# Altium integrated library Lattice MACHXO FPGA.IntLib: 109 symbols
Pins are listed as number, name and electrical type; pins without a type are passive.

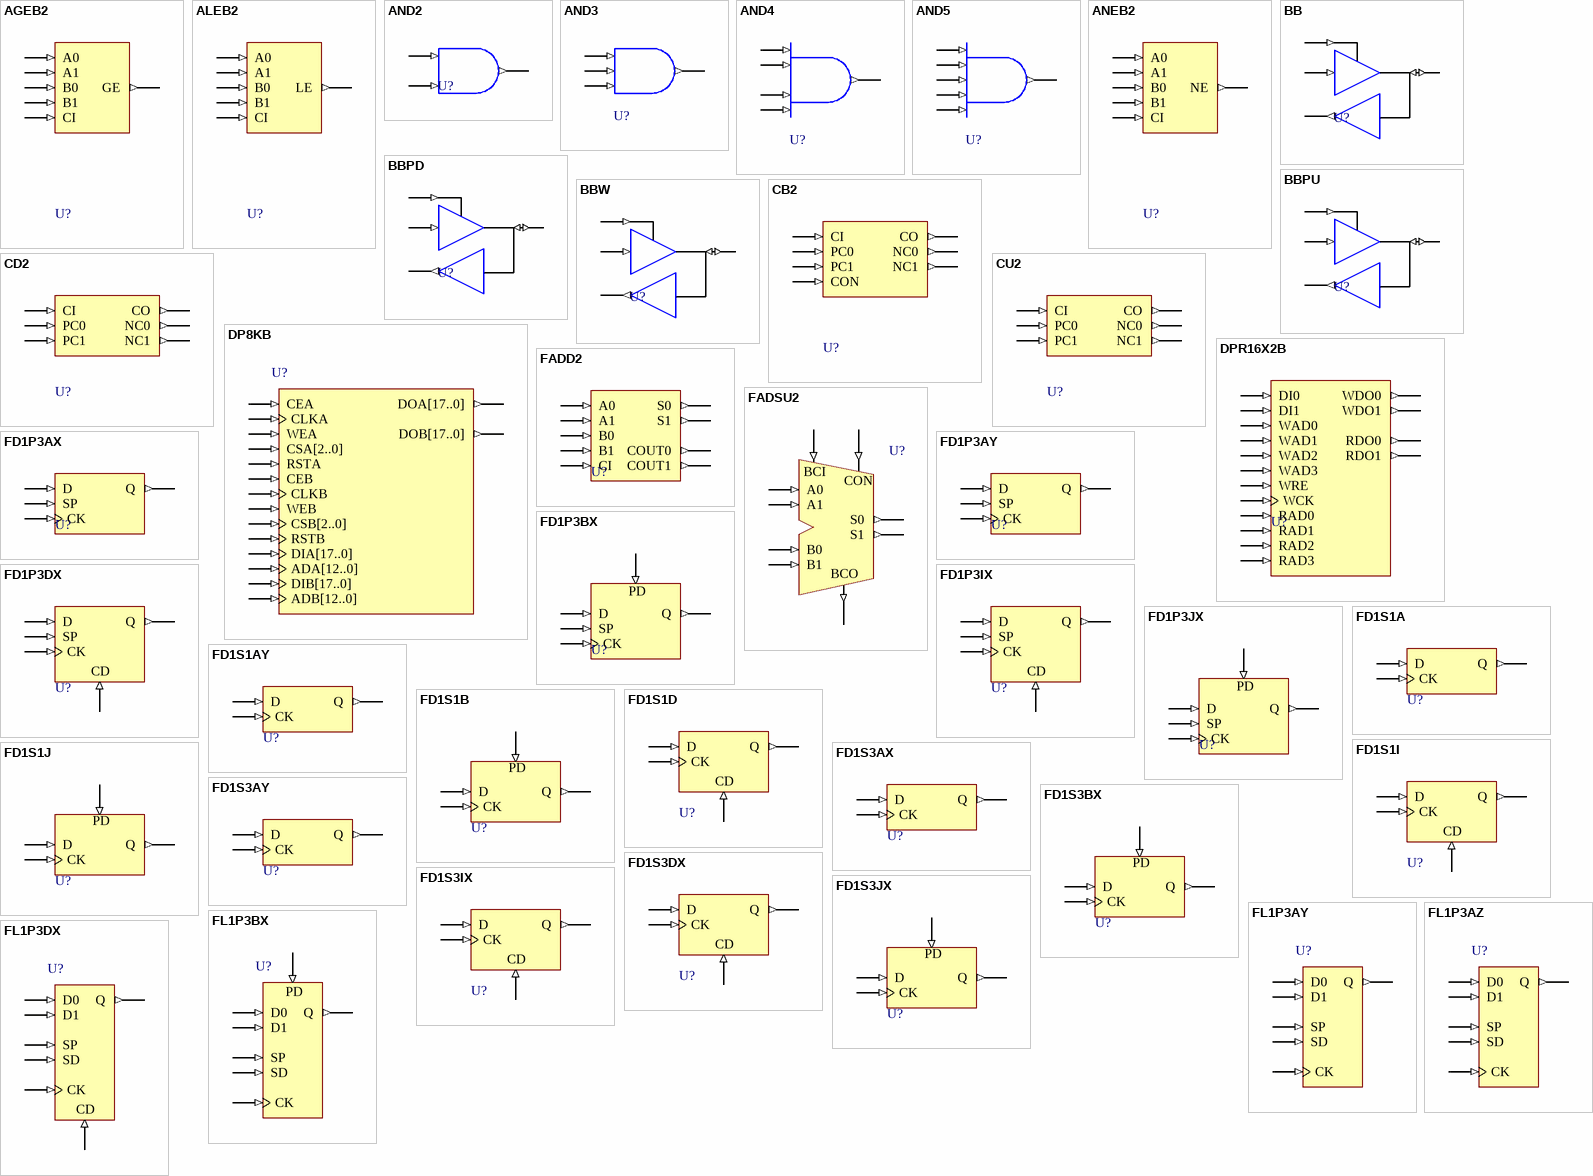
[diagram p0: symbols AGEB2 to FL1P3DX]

## AGEB2
designator U?
"A" Greater Than Or Equal To "B" (2 Bit); FPGAVendor: Lattice
pins: A0 (in), A1 (in), B0 (in), B1 (in), CI (in), GE (out)

## ALEB2
designator U?
"A"Less Than Or Equal To "B" (2 bit); FPGAVendor: Lattice
pins: A0 (in), A1 (in), B0 (in), B1 (in), CI (in), LE (out)

## AND2
designator U?
2 Input AND Gate; FPGAVendor: Lattice
pins: A (in), B (in), Z (out)

## AND3
designator U?
3 Input AND Gate; FPGAVendor: Lattice
pins: A (in), B (in), C (in), Z (out)

## AND4
designator U?
4 Input AND Gate; FPGAVendor: Lattice
pins: A (in), B (in), C (in), D (in), Z (out)

## AND5
designator U?
5 Input AND Gate; FPGAVendor: Lattice
pins: A (in), B (in), C (in), D (in), E (in), Z (out)

## ANEB2
designator U?
"A"Not Equal To "B" (2 bit); FPGAVendor: Lattice
pins: A0 (in), A1 (in), B0 (in), B1 (in), CI (in), NE (out)

## BB
designator U?
CMOS Input 6mA Sink 3mA Source Sinklim Output Buffer with Tristate – BiDirectional; FPGAVendor: Lattice
pins: B (io), I (in), O (out), T (in)

## BBPD
designator U?
CMOS Input 6mA Sink 3mA Source Sinklim Output Buffer with Tristate and Pull-down – BiDirectional; FPGAVendor: Lattice
pins: B (io), I (in), O (out), T (in)

## BBPU
designator U?
CMOS Input 6mA Sink 3mA Source Sinklim Output Buffer with Tristate and Pull-up – BiDirectional; FPGAVendor: Lattice
pins: B (io), I (in), O (out), T (in)

## BBW
designator U?
CMOS Input 6mA Sink 3mA Source Sinklim Output Buffer with Tristate – BiDirectional in keepermode; FPGAVendor: Lattice
pins: B (io), I (in), O (out), T (in)

## CB2
designator U?
LatticeXP based counter
pins: CI (in), CO (out), CON (in), NC0 (out), NC1 (out), PC0 (in), PC1 (in)

## CD2
designator U?
Combinational Logic for 2 Bit Down Counter using Look-Up Table; FPGAVendor: Lattice
pins: CI (in), CO (out), NC0 (out), NC1 (out), PC0 (in), PC1 (in)

## CU2
designator U?
Combinational Logic for 2 Bit Up Counter using Look-Up Table; FPGAVendor: Lattice
pins: CI (in), CO (out), NC0 (out), NC1 (out), PC0 (in), PC1 (in)

## DP8KB
designator U?
8K Dual Port Block RAM; FPGAVendor: Lattice
pins: ADA[12..0] (in), ADB[12..0] (in), CEA (in), CEB (in), CLKA (in), CLKB (in), CSA[2..0] (in), CSB[2..0] (in), DIA[17..0] (in), DIB[17..0] (in), DOA[17..0] (out), DOB[17..0] (out), RSTA (in), RSTB (in), WEA (in), WEB (in)

## DPR16X2B
designator U?
16 Word by 2 Dual Port RAM (within PFU); FPGAVendor: Lattice
pins: DI0 (in), DI1 (in), RAD0 (in), RAD1 (in), RAD2 (in), RAD3 (in), RDO0 (out), RDO1 (out), WAD0 (in), WAD1 (in), WAD2 (in), WAD3 (in), WCK (in), WDO0 (out), WDO1 (out), WRE (in)

## FADD2
designator U?
2 Bit Fast Adder; FPGAVendor: Lattice
pins: A0 (in), A1 (in), B0 (in), B1 (in), CI (in), COUT0 (out), COUT1 (out), S0 (out), S1 (out)

## FADSU2
designator U?
2 Bit Fast Adder/Subtracter (two’s complement); FPGAVendor: Lattice
pins: A0 (in), A1 (in), B0 (in), B1 (in), BCI (in), BCO (out), CON (in), S0 (out), S1 (out)

## FD1P3AX
designator U?
Positive Edge Triggered D Flip-Flop with Positive Level Enable, GSR used for Clear; FPGAVendor: Lattice
pins: CK (in), D (in), Q (out), SP (in)

## FD1P3AY
designator U?
Positive Edge Triggered D Flip-Flop with Positive Level Enable, GSR used for Preset; FPGAVendor: Lattice
pins: CK (in), D (in), Q (out), SP (in)

## FD1P3BX
designator U?
Positive Edge Triggered D Flip-Flop with Positive Level Enable and Positive Level Asynchronous Preset; FPGAVendor: Lattice
pins: CK (in), D (in), PD (in), Q (out), SP (in)

## FD1P3DX
designator U?
Positive Edge Triggered D Flip-Flop with Positive Level Enable and Positive Level Asynchronous Clear; FPGAVendor: Lattice
pins: CD (in), CK (in), D (in), Q (out), SP (in)

## FD1P3IX
designator U?
Positive Edge Triggered D Flip-Flop with Positive Level Synchronous Clear and Positive Level Enable (Clear overrides Enable); FPGAVendor: Lattice
pins: CD (in), CK (in), D (in), Q (out), SP (in)

## FD1P3JX
designator U?
Positive Edge Triggered D Flip-Flop with Positive Level Synchronous Preset and Positive Level Enable (Preset overrides Enable); FPGAVendor: Lattice
pins: CK (in), D (in), PD (in), Q (out), SP (in)

## FD1S1A
designator U?
Positive Level Data Latch with GSR Used for Clear; FPGAVendor: Lattice
pins: CK (in), D (in), Q (out)

## FD1S1AY
designator U?
Positive Level Data Latch with GSR Used for Preset; FPGAVendor: Lattice
pins: CK (in), D (in), Q (out)

## FD1S1B
designator U?
Positive Level Data Latch with Positive Level Asynchronous Preset; FPGAVendor: Lattice
pins: CK (in), D (in), PD (in), Q (out)

## FD1S1D
designator U?
Positive Level Data Latch with Positive Level Asynchronous Clear; FPGAVendor: Lattice
pins: CD (in), CK (in), D (in), Q (out)

## FD1S1I
designator U?
Positive Level Data Latch with Positive Level Synchronous Clear; FPGAVendor: Lattice
pins: CD (in), CK (in), D (in), Q (out)

## FD1S1J
designator U?
Positive Level Data Latch with Positive Level Synchronous Preset; FPGAVendor: Lattice
pins: CK (in), D (in), PD (in), Q (out)

## FD1S3AX
designator U?
Positive Edge Triggered D Flip-Flop, GSR Used for Clear; FPGAVendor: Lattice
pins: CK (in), D (in), Q (out)

## FD1S3AY
designator U?
Positive Edge Triggered D Flip-Flop, GSR Used for Preset; FPGAVendor: Lattice
pins: CK (in), D (in), Q (out)

## FD1S3BX
designator U?
Positive Edge Triggered D Flip-Flop with Positive Level Asynchronous Preset; FPGAVendor: Lattice
pins: CK (in), D (in), PD (in), Q (out)

## FD1S3DX
designator U?
Positive Edge Triggered D Flip-Flop with Positive Level Asynchronous Clear; FPGAVendor: Lattice
pins: CD (in), CK (in), D (in), Q (out)

## FD1S3IX
designator U?
Positive Edge Triggered D Flip-Flop with Positive Level Synchronous Clear; FPGAVendor: Lattice
pins: CD (in), CK (in), D (in), Q (out)

## FD1S3JX
designator U?
Positive Edge Triggered D Flip-Flop with Positive Level Synchronous Preset; FPGAVendor: Lattice
pins: CK (in), D (in), PD (in), Q (out)

## FL1P3AY
designator U?
Positive Edge Triggered D Flip-Flop with 2 Input Data Mux, Positive Level Data Select, and Positive Level Enable, GSR used for Preset; FPGAVendor: Lattice
pins: CK (in), D0 (in), D1 (in), Q (out), SD (in), SP (in)

## FL1P3AZ
designator U?
Positive Edge Triggered D Flip-Flop with 2 Input Data Mux, Positive Level Data Select, and Positive Level Enable, GSR used for Clear; FPGAVendor: Lattice
pins: CK (in), D0 (in), D1 (in), Q (out), SD (in), SP (in)

## FL1P3BX
designator U?
Positive Edge Triggered D Flip-Flop with 2 Input Data Mux, Positive Level Data Select, Positive Level Asynchronous Preset, and Positive Level Enable; FPGAVendor: Lattice
pins: CK (in), D0 (in), D1 (in), PD (in), Q (out), SD (in), SP (in)

## FL1P3DX
designator U?
Positive Edge Triggered D Flip-Flop with 2 Input Data Mux, Positive Level Data Select, Positive Level Asynchronous Clear, and Positive Level Enable; FPGAVendor: Lattice
pins: CD (in), CK (in), D0 (in), D1 (in), Q (out), SD (in), SP (in)

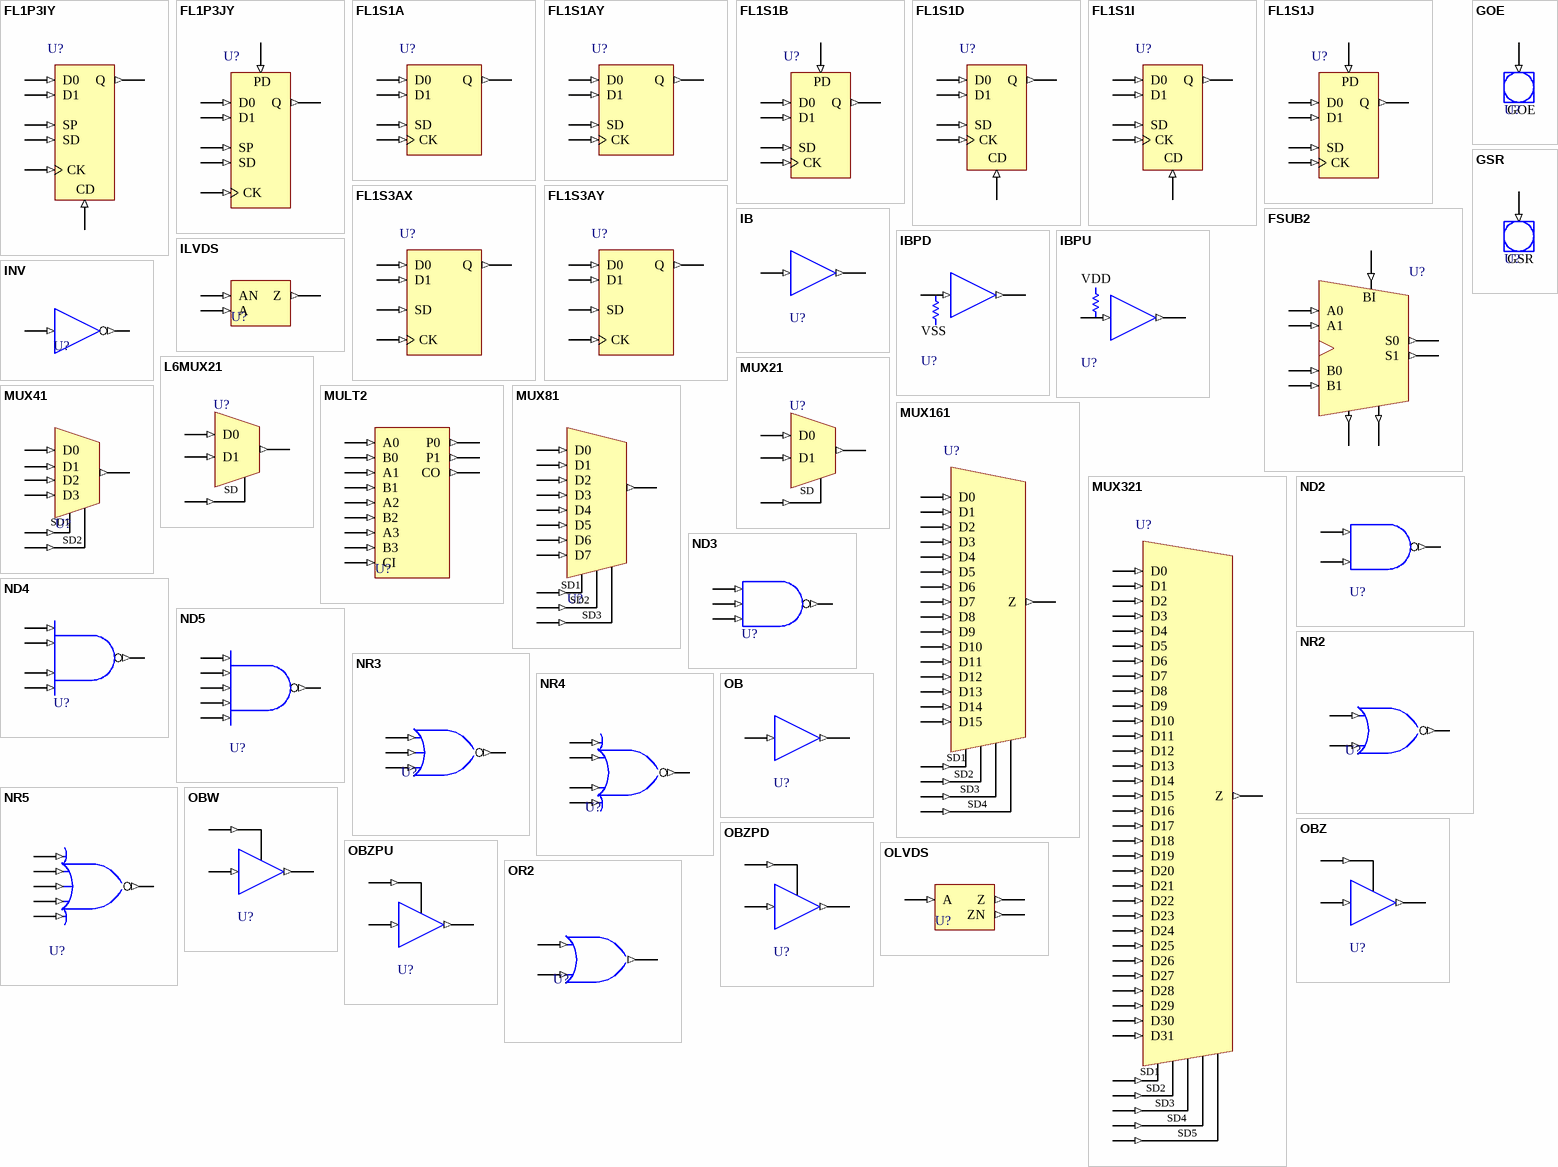
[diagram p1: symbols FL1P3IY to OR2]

## FL1P3IY
designator U?
Positive Edge Triggered D Flip-Flop with 2 Input Data Mux, Positive Level Data Select, Positive Level Synchronous Clear, and Positive Level Enable (Clear overrides Enable); FPGAVendor: Lattice
pins: CD (in), CK (in), D0 (in), D1 (in), Q (out), SD (in), SP (in)

## FL1P3JY
designator U?
Positive Edge Triggered D Flip-Flop with 2 Input Data Mux, Positive Level Data Select, Positive Level Synchronous Preset, and Positive Level Enable (Preset overrides Enable); FPGAVendor: Lattice
pins: CK (in), D0 (in), D1 (in), PD (in), Q (out), SD (in), SP (in)

## FL1S1A
designator U?
Positive Level Loadable Latch with Positive Select, GSR Used for Clear; FPGAVendor: Lattice
pins: CK (in), D0 (in), D1 (in), Q (out), SD (in)

## FL1S1AY
designator U?
Positive Level Loadable Latch with Positive Select, GSR Used for Preset; FPGAVendor: Lattice
pins: CK (in), D0 (in), D1 (in), Q (out), SD (in)

## FL1S1B
designator U?
Positive Level Loadable Latch with Positive Level Data Select and Positive Level Asynchronous Preset; FPGAVendor: Lattice
pins: CK (in), D0 (in), D1 (in), PD (in), Q (out), SD (in)

## FL1S1D
designator U?
Positive Level Loadable Latch with Positive Level Data Select and Positive Level Asynchronous Clear; FPGAVendor: Lattice
pins: CD (in), CK (in), D0 (in), D1 (in), Q (out), SD (in)

## FL1S1I
designator U?
Positive Level Loadable Latch with Positive Level Data Select and Positive Level Synchronous Clear; FPGAVendor: Lattice
pins: CD (in), CK (in), D0 (in), D1 (in), Q (out), SD (in)

## FL1S1J
designator U?
Positive Level Loadable Latch with Positive Level Data Select and Positive Level Synchronous Preset; FPGAVendor: Lattice
pins: CK (in), D0 (in), D1 (in), PD (in), Q (out), SD (in)

## FL1S3AX
designator U?
Positive Edge Triggered D Flip-Flop with 2 Input Data Mux, GSR used for Clear; FPGAVendor: Lattice
pins: CK (in), D0 (in), D1 (in), Q (out), SD (in)

## FL1S3AY
designator U?
Positive Edge Triggered D Flip-Flop with 2 Input Data Mux, GSR used for Preset; FPGAVendor: Lattice
pins: CK (in), D0 (in), D1 (in), Q (out), SD (in)

## FSUB2
designator U?
2 Bit Fast Subtracter (two’s complement); FPGAVendor: Lattice
pins: A0 (in), A1 (in), B0 (in), B1 (in), BI (in), BOUT0 (out), BOUT1 (out), S0 (out), S1 (out)

## GOE
designator U?
Global Ouput Enable; FPGAVendor: Lattice
pins: GOE (in)

## GSR
designator U?
Global Set/Reset; FPGAVendor: Lattice
pins: GSR (in)

## IB
designator U?
CMOS Input Buffer; FPGAVendor: Lattice
pins: I (in), O (out)

## IBPD
designator U?
Input Buffer with Pull-down; FPGAVendor: Lattice
pins: I (in), O (out)

## IBPU
designator U?
Input Buffer with Pull-up; FPGAVendor: Lattice
pins: I (in), O (out)

## ILVDS
designator U?
LVDS Input Buffer; FPGAVendor: Lattice
pins: A (in), AN (in), Z (out)

## INV
designator U?
Inverter; FPGAVendor: Lattice
pins: A (in), Z (out)

## L6MUX21
designator U?
2 to 1 Mux; FPGAVendor: Lattice
pins: D0 (in), D1 (in), SD (in), Z (out)

## MULT2
designator U?
2x2 Multiplier; FPGAVendor: Lattice
pins: A0 (in), A1 (in), A2 (in), A3 (in), B0 (in), B1 (in), B2 (in), B3 (in), CI (in), CO (out), P0 (out), P1 (out)

## MUX21
designator U?
2 to 1 Mux; FPGAVendor: Lattice
pins: D0 (in), D1 (in), SD (in), Z (out)

## MUX41
designator U?
4 to 1 Mux; FPGAVendor: Lattice
pins: D0 (in), D1 (in), D2 (in), D3 (in), SD1 (in), SD2 (in), Z (out)

## MUX81
designator U?
8 to 1 Mux; FPGAVendor: Lattice
pins: D0 (in), D1 (in), D2 (in), D3 (in), D4 (in), D5 (in), D6 (in), D7 (in), SD1 (in), SD2 (in), SD3 (in), Z (out)

## MUX161
designator U?
16 to 1 Mux in PFU; FPGAVendor: Lattice
pins: D0 (in), D1 (in), D2 (in), D3 (in), D4 (in), D5 (in), D6 (in), D7 (in), D8 (in), D9 (in), D10 (in), D11 (in), D12 (in), D13 (in), D14 (in), D15 (in), SD1 (in), SD2 (in), SD3 (in), SD4 (in), Z (out)

## MUX321
designator U?
32 to 1 Mux; FPGAVendor: Lattice
pins: D0 (in), D1 (in), D2 (in), D3 (in), D4 (in), D5 (in), D6 (in), D7 (in), D8 (in), D9 (in), D10 (in), D11 (in), D12 (in), D13 (in), D14 (in), D15 (in), D16 (in), D17 (in), D18 (in), D19 (in), D20 (in), D21 (in), D22 (in), D23 (in), D24 (in), D25 (in), D26 (in), D27 (in), D28 (in), D29 (in), D30 (in), D31 (in), SD1 (in), SD2 (in), SD3 (in), SD4 (in), SD5 (in), Z (out)

## ND2
designator U?
2 Input NAND Gate; FPGAVendor: Lattice
pins: A (in), B (in), Z (out)

## ND3
designator U?
3 Input NAND Gate; FPGAVendor: Lattice
pins: A (in), B (in), C (in), Z (out)

## ND4
designator U?
4 Input NAND Gate; FPGAVendor: Lattice
pins: A (in), B (in), C (in), D (in), Z (out)

## ND5
designator U?
5 Input NAND Gate; FPGAVendor: Lattice
pins: A (in), B (in), C (in), D (in), E (in), Z (out)

## NR2
designator U?
2 Input NOR Gate; FPGAVendor: Lattice
pins: A (in), B (in), Z (out)

## NR3
designator U?
3 Input NOR Gate; FPGAVendor: Lattice
pins: A (in), B (in), C (in), Z (out)

## NR4
designator U?
4 Input NOR Gate; FPGAVendor: Lattice
pins: A (in), B (in), C (in), D (in), Z (out)

## NR5
designator U?
5 Input NOR Gate; FPGAVendor: Lattice
pins: A (in), B (in), C (in), D (in), E (in), Z (out)

## OB
designator U?
Output Buffer; FPGAVendor: Lattice
pins: I (in), O (out)

## OBW
designator U?
6mA Sink 3mA Source Sinklim Output Buffer with Tristate; FPGAVendor: Lattice
pins: I (in), O (out), T (in)

## OBZ
designator U?
6mA Sink 3mA Source Sinklim Output Buffer; FPGAVendor: Lattice
pins: I (in), O (out), T (in)

## OBZPD
designator U?
12mA Sink 6mA Source Slewlim Output Buffer; FPGAVendor: Lattice
pins: I (in), O (out), T (in)

## OBZPU
designator U?
12mA Sink 6mA Source Fast Output Buffer; FPGAVendor: Lattice
pins: I (in), O (out), T (in)

## OLVDS
designator U?
LVDS Output Buffer; FPGAVendor: Lattice
pins: A (in), Z (out), ZN (out)

## OR2
designator U?
2 Input OR Gate; FPGAVendor: Lattice
pins: A (in), B (in), Z (out)

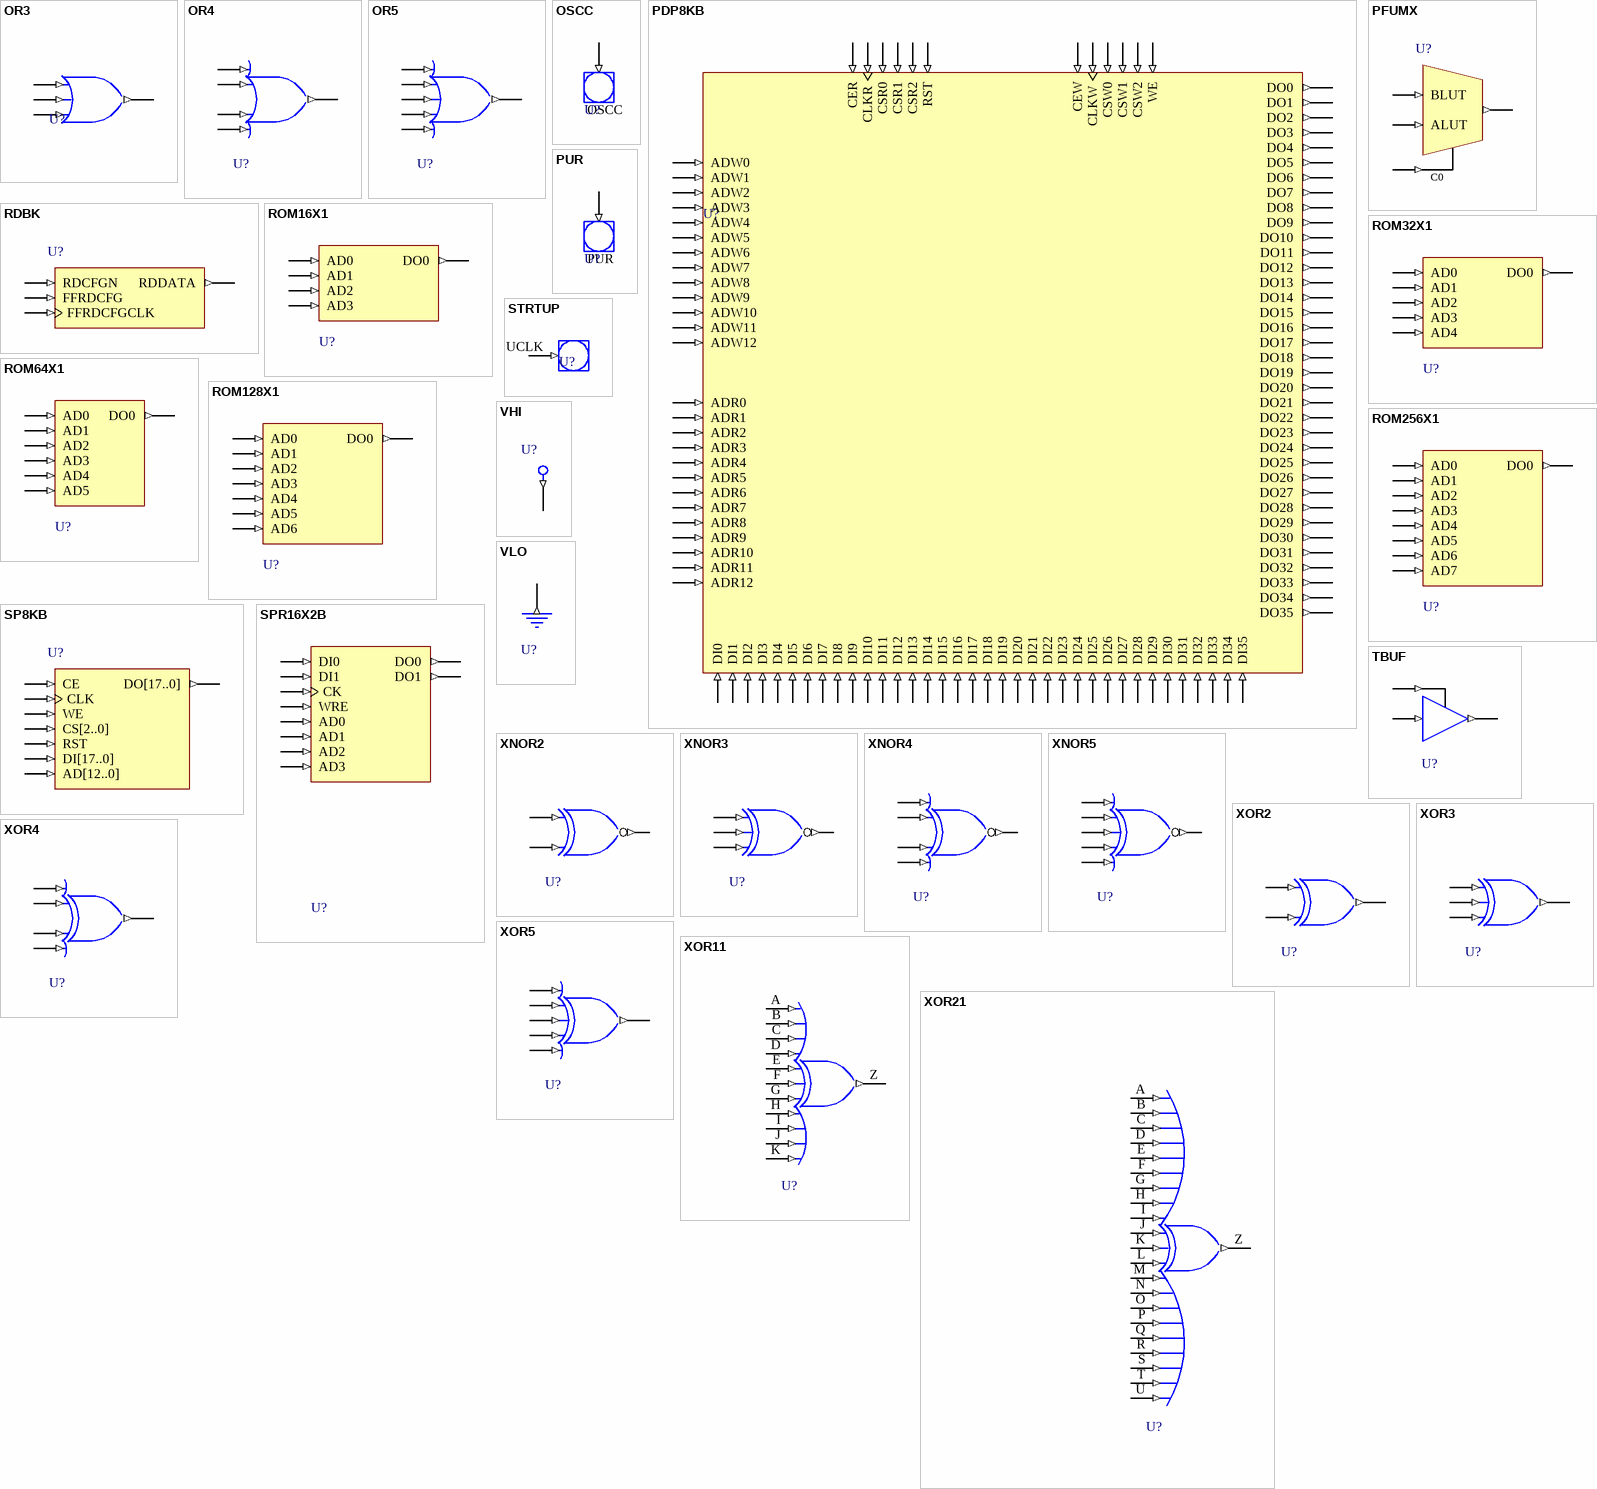
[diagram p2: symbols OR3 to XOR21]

## OR3
designator U?
3 Input OR Gate; FPGAVendor: Lattice
pins: A (in), B (in), C (in), Z (out)

## OR4
designator U?
4 Input OR Gate; FPGAVendor: Lattice
pins: A (in), B (in), C (in), D (in), Z (out)

## OR5
designator U?
5 Input OR Gate; FPGAVendor: Lattice
pins: A (in), B (in), C (in), D (in), E (in), Z (out)

## OSCC
designator U?
Internal Oscillator; FPGAVendor: Lattice
pins: OSC (in)

## PDP8KB
designator U?
8K Pseudo Dual Port Block RAM; FPGAVendor: Lattice
pins: ADR0 (in), ADR1 (in), ADR2 (in), ADR3 (in), ADR4 (in), ADR5 (in), ADR6 (in), ADR7 (in), ADR8 (in), ADR9 (in), ADR10 (in), ADR11 (in), ADR12 (in), ADW0 (in), ADW1 (in), ADW2 (in), ADW3 (in), ADW4 (in), ADW5 (in), ADW6 (in), ADW7 (in), ADW8 (in), ADW9 (in), ADW10 (in), ADW11 (in), ADW12 (in), CER (in), CEW (in), CLKR (in), CLKW (in), CSR0 (in), CSR1 (in), CSR2 (in), CSW0 (in), CSW1 (in), CSW2 (in), DI0 (in), DI1 (in), DI2 (in), DI3 (in), DI4 (in), DI5 (in), DI6 (in), DI7 (in), DI8 (in), DI9 (in), DI10 (in), DI11 (in), DI12 (in), DI13 (in), DI14 (in), DI15 (in), DI16 (in), DI17 (in), DI18 (in), DI19 (in), DI20 (in), DI21 (in), DI22 (in), DI23 (in), DI24 (in), DI25 (in), DI26 (in), DI27 (in), DI28 (in), DI29 (in), DI30 (in), DI31 (in), DI32 (in), DI33 (in), DI34 (in), DI35 (in), DO0 (out), DO1 (out), DO2 (out), DO3 (out), DO4 (out), DO5 (out), DO6 (out), DO7 (out), DO8 (out), DO9 (out), DO10 (out), DO11 (out), DO12 (out), DO13 (out), DO14 (out), DO15 (out), DO16 (out), DO17 (out), DO18 (out), DO19 (out), DO20 (out), DO21 (out), DO22 (out), DO23 (out), DO24 (out), DO25 (out), DO26 (out), DO27 (out), DO28 (out), DO29 (out), DO30 (out), DO31 (out), DO32 (out), DO33 (out), DO34 (out), DO35 (out), RST (in), WE (in)

## PFUMX
designator U?
PFU Mux; FPGAVendor: Lattice
pins: ALUT (in), BLUT (in), C0 (in), Z (out)

## PUR
designator U?
Power Up Set/Reset; FPGAVendor: Lattice
pins: PUR (in)

## RDBK
designator U?
Readback Controller; FPGAVendor: Lattice
pins: FFRDCFG (in), FFRDCFGCLK (in), RDCFGN (in), RDDATA (out)

## ROM16X1
designator U?
16 Word by 1 Bit Read-Only Memory; FPGAVendor: Lattice
pins: AD0 (in), AD1 (in), AD2 (in), AD3 (in), DO0 (out)

## ROM32X1
designator U?
32 Word by 1 Bit Read-Only Memory; FPGAVendor: Lattice
pins: AD0 (in), AD1 (in), AD2 (in), AD3 (in), AD4 (in), DO0 (out)

## ROM64X1
designator U?
64 Word by 1 Bit Read-Only Memory; FPGAVendor: Lattice
pins: AD0 (in), AD1 (in), AD2 (in), AD3 (in), AD4 (in), AD5 (in), DO0 (out)

## ROM128X1
designator U?
128 Word by 1 Bit Read-Only Memory; FPGAVendor: Lattice
pins: AD0 (in), AD1 (in), AD2 (in), AD3 (in), AD4 (in), AD5 (in), AD6 (in), DO0 (out)

## ROM256X1
designator U?
256 Word by 1 Bit Read-Only Memory; FPGAVendor: Lattice
pins: AD0 (in), AD1 (in), AD2 (in), AD3 (in), AD4 (in), AD5 (in), AD6 (in), AD7 (in), DO0 (out)

## SP8KB
designator U?
8 Word by 8 Bit Single Port Block RAM; FPGAVendor: Lattice
pins: AD[12..0] (in), CE (in), CLK (in), CS[2..0] (in), DI[17..0] (in), DO[17..0] (out), RST (in), WE (in)

## SPR16X2B
designator U?
16 Word by 2 Single Port RAM (within PFU); FPGAVendor: Lattice
pins: AD0 (in), AD1 (in), AD2 (in), AD3 (in), CK (in), DI0 (in), DI1 (in), DO0 (out), DO1 (out), WRE (in)

## STRTUP
designator U?
Startup Controller; FPGAVendor: Lattice
pins: UCLK (in)

## TBUF
designator U?
Internal Buffer with Tristate (used in SLIC area only); FPGAVendor: Lattice
pins: I (in), O (out), T (in)

## VHI
designator U?
Logic High Generator; FPGAVendor: Lattice
pins: Z (out)

## VLO
designator U?
Logic Low Generator; FPGAVendor: Lattice
pins: Z (out)

## XNOR2
designator U?
2 Input Exclusive NOR Gate; FPGAVendor: Lattice
pins: A (in), B (in), Z (out)

## XNOR3
designator U?
3 Input Exclusive NOR Gate; FPGAVendor: Lattice
pins: A (in), B (in), C (in), Z (out)

## XNOR4
designator U?
4 Input Exclusive NOR Gate; FPGAVendor: Lattice
pins: A (in), B (in), C (in), D (in), Z (out)

## XNOR5
designator U?
5 Input Exclusive NOR Gate; FPGAVendor: Lattice
pins: A (in), B (in), C (in), D (in), E (in), Z (out)

## XOR2
designator U?
2 Input Exclusive OR Gate; FPGAVendor: Lattice
pins: A (in), B (in), Z (out)

## XOR3
designator U?
3 Input Exclusive OR Gate; FPGAVendor: Lattice
pins: A (in), B (in), C (in), Z (out)

## XOR4
designator U?
4 Input Exclusive OR Gate; FPGAVendor: Lattice
pins: A (in), B (in), C (in), D (in), Z (out)

## XOR5
designator U?
5 Input Exclusive OR Gate; FPGAVendor: Lattice
pins: A (in), B (in), C (in), D (in), E (in), Z (out)

## XOR11
designator U?
11-Input Exclusive OR Gate; FPGAVendor: Lattice
pins: A (in), B (in), C (in), D (in), E (in), F (in), G (in), H (in), I (in), J (in), K (in), Z (out)

## XOR21
designator U?
21-Input Exclusive OR Gate; FPGAVendor: Lattice
pins: A (in), B (in), C (in), D (in), E (in), F (in), G (in), H (in), I (in), J (in), K (in), L (in), M (in), N (in), O (in), P (in), Q (in), R (in), S (in), T (in), U (in), Z (out)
